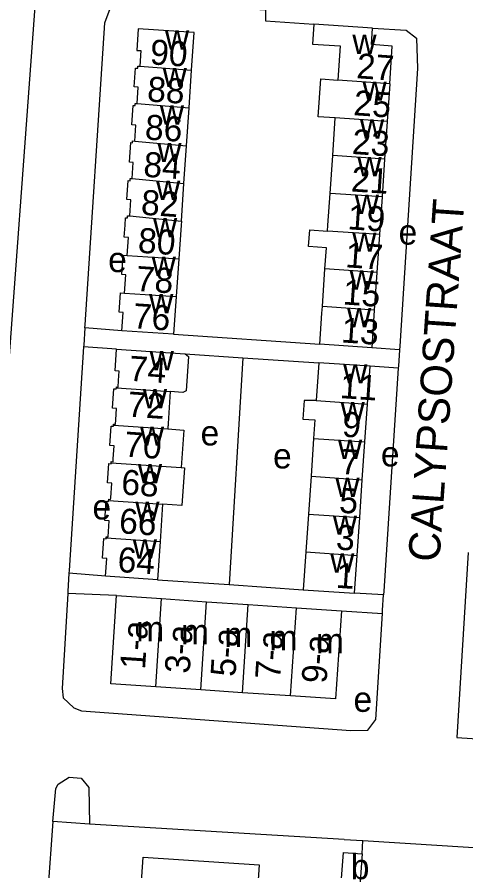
# Model space of a CAD drawing. Extents: x 161773 to 163836, y 384796 to 386521.
# Drawn here: x 162049.5 to 162121.2, y 386146.9 to 386283.2 of the extents above; entities that cross this region are included whole.
import ezdxf

# ---------------------------------------------------------------- set-up
doc = ezdxf.new("R2010")
doc.units = 0
for name, color, linetype in [('BLT_Basislijn', 7, 'Continuous'), ('BLT_Bebouwing', 7, 'Continuous'), ('BLT_Centroide', 7, 'Continuous'), ('BLT_Huisnummer', 7, 'Continuous'), ('BLT_Huisnummer_ tussenligend', 7, 'Continuous'), ('BLT_Huisnummer_reeks', 7, 'Continuous'), ('BLT_Onderverdeling_panden', 7, 'Continuous'), ('BLT_Straatnaam', 7, 'Continuous')]:
    doc.layers.add(name, color=color, linetype=linetype)

msp = doc.modelspace()

# ---------------------------------------------------------------- linework, layer by layer
at = {"layer": 'BLT_Basislijn'}
for p, q in [((162047.33, 386216.15), (162056.95, 386346.98)), ((162066.26, 386233.17), (162060.34, 386233.61)), ((162074.51, 386232.61), (162097.83, 386231)), ((162065.4, 386230.23), (162060.13, 386230.58)), ((162110.56, 386230.14), (162106.12, 386230.43)), ((162076.36, 386229.49), (162085.56, 386228.87)), ((162085.56, 386228.87), (162083.39, 386192.64)), ((162085.56, 386228.87), (162097.67, 386228.05)), ((162110.35, 386227.19), (162105.87, 386227.49)), ((162063.64, 386194), (162057.79, 386194.49)), ((162071.91, 386193.43), (162083.39, 386192.64)), ((162083.39, 386192.64), (162095.19, 386191.83)), ((162065.41, 386190.88), (162057.61, 386191.23)), ((162108.02, 386191), (162103.38, 386191.27)), ((162101.29, 386188.48), (162107.82, 386188.03)), ((162055.22, 386154.83), (162051.7, 386105.26)), ((162061.06, 386154.42), (162055.22, 386154.83)), ((162088.43, 386152.77), (162061.06, 386154.42)), ((162101.7, 386151.96), (162088.43, 386152.77)), ((162101.7, 386151.96), (162104.72, 386151.78)), ((162104.58, 386149.66), (162104.72, 386151.78)), ((162104.72, 386151.78), (162117.39, 386151.01)), ((162117.39, 386151.01), (162123.24, 386150.61))]:
    msp.add_line(p, q, dxfattribs=at)
for points in [[(162060.34, 386233.61), (162060.37, 386234.09), (162063.55, 386282.31), (162064.37, 386284.59), (162065.99, 386285.78), (162089.17, 386284.41), (162089.19, 386282.64), (162096.88, 386282.13)], [(162106.27, 386281.48), (162111.61, 386281.14), (162113.26, 386279.86), (162113.42, 386275.03), (162110.6, 386230.72), (162110.56, 386230.14)], [(162060.34, 386233.61), (162060.15, 386230.86), (162060.13, 386230.58)], [(162060.13, 386230.58), (162057.82, 386194.88), (162057.79, 386194.49)], [(162110.56, 386230.14), (162110.37, 386227.53), (162110.35, 386227.19)], [(162110.35, 386227.19), (162108.06, 386191.57), (162108.02, 386191)], [(162121.52, 386197.75), (162119.71, 386168.25), (162143.32, 386166.67), (162206.87, 386162.41)], [(162057.79, 386194.49), (162057.63, 386191.55), (162057.61, 386191.23)], [(162057.61, 386191.23), (162056.74, 386176.08), (162056.9, 386174.56), (162058.6, 386172.97), (162059.81, 386172.49), (162102.78, 386169.36), (162105.52, 386169.41), (162106.76, 386171.1), (162107.82, 386188.03)], [(162107.82, 386188.03), (162107.85, 386188.59), (162108.02, 386191)], [(162055.22, 386154.83), (162055.73, 386160.1), (162056.09, 386160.77), (162057.84, 386161.92), (162059.76, 386161.72), (162060.96, 386160.24), (162061.06, 386154.42)]]:
    msp.add_lwpolyline(points, dxfattribs=at)
at = {"layer": 'BLT_Bebouwing'}
for p, q in [((162106.27, 386281.48), (162096.88, 386282.13)), ((162076.96, 386268.73), (162077.37, 386274.75)), ((162109, 386272.6), (162108.59, 386266.58)), ((162076.56, 386262.71), (162076.96, 386268.73)), ((162099.89, 386261.12), (162100.3, 386267.15)), ((162108.59, 386266.58), (162108.18, 386260.55)), ((162076.15, 386256.69), (162076.56, 386262.71)), ((162099.48, 386255.1), (162099.89, 386261.12)), ((162108.18, 386260.55), (162107.77, 386254.53)), ((162075.75, 386250.67), (162076.15, 386256.69)), ((162107.77, 386254.53), (162107.35, 386248.51)), ((162067.32, 386251.5), (162067.49, 386251.49)), ((162107.35, 386248.51), (162106.94, 386242.48)), ((162075.34, 386244.65), (162074.93, 386238.63)), ((162098.24, 386237.03), (162098.65, 386243.05)), ((162106.94, 386242.48), (162106.53, 386236.46)), ((162074.93, 386238.63), (162074.51, 386232.61)), ((162106.53, 386236.46), (162106.12, 386230.43)), ((162074.51, 386232.61), (162066.26, 386233.17)), ((162106.12, 386230.43), (162097.83, 386231)), ((162065.4, 386230.23), (162076.36, 386229.49)), ((162097.67, 386228.05), (162097.26, 386222.01)), ((162105.87, 386227.49), (162097.67, 386228.05)), ((162105.45, 386221.45), (162105.87, 386227.49)), ((162073.97, 386223.46), (162073.56, 386217.5)), ((162105.04, 386215.42), (162105.45, 386221.45)), ((162073.62, 386218.39), (162073.57, 386217.63)), ((162096.84, 386215.98), (162096.43, 386209.94)), ((162104.62, 386209.38), (162105.04, 386215.42)), ((162096.43, 386209.94), (162096.02, 386203.9)), ((162104.21, 386203.34), (162104.62, 386209.38)), ((162072.74, 386205.5), (162072.33, 386199.53)), ((162096.02, 386203.9), (162095.6, 386197.87)), ((162103.8, 386197.3), (162104.21, 386203.34)), ((162072.33, 386199.53), (162071.91, 386193.43)), ((162095.6, 386197.87), (162095.19, 386191.83)), ((162103.38, 386191.27), (162103.8, 386197.3)), ((162071.91, 386193.43), (162063.64, 386194)), ((162065.41, 386190.88), (162072.58, 386190.4)), ((162095.19, 386191.83), (162103.38, 386191.27)), ((162072.58, 386190.4), (162079.76, 386189.92)), ((162079.76, 386189.92), (162086.41, 386189.48)), ((162094.11, 386188.96), (162101.29, 386188.48)), ((162078.82, 386175.84), (162071.64, 386176.32)), ((162085.47, 386175.39), (162078.82, 386175.84)), ((162093.17, 386174.88), (162085.47, 386175.39)), ((162101.6, 386149.88), (162104.58, 386149.66)), ((162104.58, 386149.66), (162103.97, 386141.37))]:
    msp.add_line(p, q, dxfattribs=at)
for points in [[(162077.37, 386274.75), (162077.77, 386280.77), (162068.87, 386281.37), (162068.64, 386277.93), (162069.27, 386277.89), (162069.11, 386275.39)], [(162096.88, 386282.13), (162096.66, 386278.93), (162101.08, 386278.63), (162100.71, 386273.17)], [(162109, 386272.6), (162109.41, 386278.62), (162106.09, 386278.85), (162106.27, 386281.48)], [(162068.66, 386269.43), (162068.84, 386272.03), (162068.22, 386272.08), (162068.42, 386275.1), (162068.78, 386275.08), (162068.8, 386275.41), (162069.11, 386275.39)], [(162100.3, 386267.15), (162097.57, 386267.33), (162097.98, 386273.36), (162100.71, 386273.17)], [(162068.3, 386263.45), (162068.47, 386265.98), (162067.81, 386266.02), (162068.02, 386269.15), (162068.36, 386269.13), (162068.38, 386269.44), (162068.66, 386269.43)], [(162067.87, 386257.46), (162068.04, 386260.02), (162067.44, 386260.06), (162067.65, 386263.2), (162067.95, 386263.18), (162067.96, 386263.47), (162068.3, 386263.45)], [(162067.49, 386251.49), (162067.66, 386254.06), (162067.04, 386254.1), (162067.24, 386257.15), (162067.55, 386257.12), (162067.58, 386257.48), (162067.87, 386257.46)], [(162099.07, 386249.07), (162099.13, 386250), (162099.48, 386255.1)], [(162067.08, 386245.17), (162067.28, 386248.05), (162066.62, 386248.1), (162066.76, 386250), (162066.84, 386251.2), (162067.14, 386251.18), (162067.16, 386251.51), (162067.32, 386251.5)], [(162075.75, 386250.67), (162075.71, 386250), (162075.34, 386244.65)], [(162098.65, 386243.05), (162098.88, 386246.41), (162096.04, 386246.61), (162096.22, 386249.27), (162099.07, 386249.07)], [(162066.65, 386239.19), (162066.85, 386242.09), (162066.23, 386242.13), (162066.44, 386245.21), (162067.08, 386245.17)], [(162066.26, 386233.17), (162066.46, 386236.09), (162065.81, 386236.14), (162066.02, 386239.24), (162066.65, 386239.19)], [(162097.83, 386231), (162098.17, 386235.99), (162098.24, 386237.03)], [(162065.72, 386225.2), (162065.82, 386226.72), (162065.16, 386226.76), (162065.4, 386230.23)], [(162076.36, 386229.49), (162076.86, 386229.05), (162076.49, 386223.58)], [(162065.36, 386224.05), (162065.37, 386224.2), (162065.65, 386224.18), (162065.72, 386225.2)], [(162065.27, 386218.96), (162065.4, 386220.78), (162064.76, 386220.83), (162064.97, 386223.92), (162065.35, 386223.9), (162065.36, 386224.05)], [(162076.49, 386223.58), (162076, 386223.32), (162073.97, 386223.46)], [(162097.26, 386222.01), (162095.35, 386222.04), (162095.15, 386219.08), (162097.05, 386218.95), (162096.84, 386215.98)], [(162064.92, 386218.1), (162064.93, 386218.27), (162065.22, 386218.24), (162065.27, 386218.96)], [(162064.87, 386212.72), (162065.02, 386214.79), (162064.34, 386214.84), (162064.56, 386217.95), (162064.91, 386217.93), (162064.92, 386218.1)], [(162073.56, 386217.5), (162076.12, 386217.32), (162075.7, 386211.33)], [(162064.52, 386212.1), (162064.54, 386212.27), (162064.84, 386212.25), (162064.87, 386212.72)], [(162064.47, 386206.48), (162064.63, 386208.85), (162063.94, 386208.89), (162064.15, 386211.96), (162064.51, 386211.94), (162064.52, 386212.1)], [(162075.7, 386211.33), (162076.24, 386211.3), (162075.83, 386205.28), (162072.74, 386205.5)], [(162064.03, 386200.26), (162064.21, 386202.82), (162063.53, 386202.86), (162063.74, 386205.95), (162064.12, 386205.92), (162064.13, 386206.09)], [(162064.13, 386206.09), (162064.14, 386206.26), (162064.45, 386206.24), (162064.47, 386206.48)], [(162063.64, 386194), (162063.84, 386196.82), (162063.14, 386196.87), (162063.36, 386200), (162063.73, 386199.97), (162063.74, 386200.12)], [(162063.74, 386200.12), (162063.75, 386200.27), (162064.03, 386200.26)], [(162071.64, 386176.32), (162064.47, 386176.8), (162065.41, 386190.88)], [(162086.41, 386189.48), (162094.11, 386188.96)], [(162101.29, 386188.48), (162100.35, 386174.4), (162093.17, 386174.88)], [(162098.44, 386105.83), (162066.84, 386107.94), (162067.4, 386116.31), (162069.63, 386149.16), (162088.15, 386147.92)], [(162103.97, 386141.37), (162100.99, 386141.59), (162101.6, 386149.88)], [(162088.15, 386147.92), (162086.71, 386126.45), (162085.67, 386126.52), (162085.5, 386123.94), (162096.52, 386123.2), (162096.06, 386116.26), (162095.21, 386116.32), (162095.09, 386114.46), (162099, 386114.2), (162098.44, 386105.83)]]:
    msp.add_lwpolyline(points, dxfattribs=at)
at = {"layer": 'BLT_Onderverdeling_panden'}
for p, q in [((162069.11, 386275.39), (162077.37, 386274.75)), ((162109, 386272.6), (162100.71, 386273.17)), ((162068.66, 386269.43), (162076.96, 386268.73)), ((162108.59, 386266.58), (162100.3, 386267.15)), ((162068.3, 386263.45), (162076.56, 386262.71)), ((162108.18, 386260.55), (162099.89, 386261.12)), ((162067.87, 386257.46), (162076.15, 386256.69)), ((162107.77, 386254.53), (162099.48, 386255.1)), ((162067.49, 386251.49), (162075.75, 386250.67)), ((162107.35, 386248.51), (162099.07, 386249.07)), ((162067.08, 386245.17), (162075.34, 386244.65)), ((162106.94, 386242.48), (162098.65, 386243.05)), ((162066.65, 386239.19), (162074.93, 386238.63)), ((162106.53, 386236.46), (162098.24, 386237.03)), ((162065.36, 386224.05), (162073.97, 386223.46)), ((162097.26, 386222.01), (162105.45, 386221.45)), ((162064.92, 386218.1), (162073.56, 386217.5)), ((162096.84, 386215.98), (162105.04, 386215.42)), ((162064.52, 386212.1), (162075.7, 386211.33)), ((162096.43, 386209.94), (162104.62, 386209.38)), ((162064.13, 386206.09), (162072.74, 386205.5)), ((162096.02, 386203.9), (162104.21, 386203.34)), ((162063.74, 386200.12), (162072.33, 386199.53)), ((162095.6, 386197.87), (162103.8, 386197.3)), ((162071.64, 386176.32), (162072.58, 386190.4)), ((162078.82, 386175.84), (162079.76, 386189.92)), ((162085.47, 386175.39), (162086.41, 386189.48)), ((162093.17, 386174.88), (162094.11, 386188.96))]:
    msp.add_line(p, q, dxfattribs=at)

# ---------------------------------------------------------------- texts
at = {"layer": 'BLT_Centroide'}
for s, p in [('w', (162073.12, 386278.06)), ('w', (162103.03, 386277.36)), ('w', (162072.75, 386272.06)), ('w', (162104.65, 386269.88)), ('w', (162072.3, 386266.06)), ('w', (162104.24, 386263.84)), ('w', (162071.91, 386260.09)), ('w', (162103.83, 386257.81)), ('w', (162071.7, 386254.06)), ('w', (162103.41, 386251.81)), ('w', (162071.21, 386248.09)), ('e', (162110.41, 386246.92)), ('w', (162103.01, 386245.78)), ('e', (162064.06, 386242.53)), ('w', (162071, 386241.91)), ('w', (162102.59, 386239.75)), ('w', (162070.59, 386235.94)), ('w', (162102.18, 386233.72)), ('w', (162070.67, 386226.84)), ('w', (162101.56, 386224.75)), ('w', (162069.59, 386220.78)), ('w', (162101.15, 386218.72)), ('w', (162069.13, 386214.81)), ('e', (162078.81, 386214.86)), ('w', (162100.73, 386212.69)), ('e', (162090.37, 386211.19)), ('e', (162107.59, 386211.51)), ('w', (162068.8, 386208.81)), ('w', (162100.32, 386206.62)), ('e', (162061.55, 386203.04)), ('w', (162068.38, 386202.81)), ('w', (162099.91, 386200.59)), ('w', (162067.98, 386196.78)), ('w', (162099.49, 386194.56)), ('m', (162068.53, 386183.59)), ('m', (162075.7, 386183.11)), ('m', (162082.61, 386182.66)), ('m', (162089.8, 386182.17)), ('m', (162097.23, 386181.67)), ('e', (162103.21, 386172.33)), ('b', (162102.78, 386145.62))]:
    msp.add_text(s, height=4, dxfattribs=at).set_placement(p)
at = {"layer": 'BLT_Huisnummer'}
for s, rotation, p in [('90', 356.1301, (162070.65, 386275.71)), ('27', 356.0837, (162103.61, 386273.49)), ('84', 356.1273, (162069.6, 386257.77)), ('21', 356.0878, (162102.74, 386255.42)), ('80', 356.129, (162068.73, 386245.64)), ('17', 356.0854, (162101.83, 386243.31)), ('76', 356.0746, (162067.91, 386233.58)), ('13', 356.063, (162101.18, 386231.32)), ('74', 356.0772, (162067.27, 386225.2)), ('11', 356.0769, (162100.95, 386222.43)), ('68', 356.0787, (162066.06, 386207.04)), ('5', 356.0769, (162100.84, 386204.14)), ('64', 356.0655, (162065.47, 386194.68)), ('1', 356.0769, (162100.32, 386192.15))]:
    msp.add_text(s, height=4, rotation=rotation, dxfattribs=at).set_placement(p)
at = {"layer": 'BLT_Huisnummer_ tussenligend'}
for s, rotation, p in [('88', 356.1273, (162070.2, 386269.79)), ('25', 356.0878, (162103.13, 386267.59)), ('86', 356.1273, (162069.84, 386263.72)), ('23', 356.0878, (162102.89, 386261.4)), ('82', 356.129, (162069.22, 386251.71)), ('19', 356.0854, (162102.2, 386249.38)), ('78', 356.0746, (162068.39, 386239.53)), ('15', 356.063, (162101.42, 386237.38)), ('72', 356.0772, (162067.04, 386219.49)), ('9', 356.0769, (162101.31, 386216.28)), ('70', 356.0787, (162066.53, 386213.1)), ('7', 356.0769, (162101.06, 386210.33)), ('66', 356.0655, (162065.71, 386200.86)), ('3', 356.0769, (162100.35, 386198.25))]:
    msp.add_text(s, height=4, rotation=rotation, dxfattribs=at).set_placement(p)
at = {"layer": 'BLT_Huisnummer_reeks'}
for s, rotation, p in [('1-a', 86.177, (162069.93, 386179.04)), ('3-a', 86.1808, (162077.06, 386178.37)), ('5-a', 86.1811, (162084.37, 386177.86)), ('7-a', 86.1808, (162091.49, 386177.44)), ('9-a', 86.1808, (162098.91, 386176.79))]:
    msp.add_text(s, height=4, rotation=rotation, dxfattribs=at).set_placement(p)
at = {"layer": 'BLT_Straatnaam'}
msp.add_text('CALYPSOSTRAAT', height=5, rotation=86.0449, dxfattribs=at).set_placement((162116.92, 386196.16))

doc.saveas('drawing.dxf')
